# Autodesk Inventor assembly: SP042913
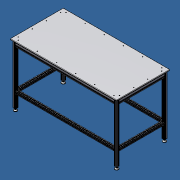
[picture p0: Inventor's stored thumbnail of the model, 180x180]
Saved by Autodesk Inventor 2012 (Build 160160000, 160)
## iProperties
Created: 2013-04
Part Number: SP042913
Document SubType Name: Assembly
Designer: Admin
Author: Admin
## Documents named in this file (8)
- C:\Andys Backup Data\ANDY'S INVENTOR\INVENTOR LIBRARIES\ASSEMBLY LIBRARY\45 SERIES\TABLES_CARTS\SP042913 MEDIUM DUTY TABLE\SP042913 MEDIUM DUTY TABLE.iam
- C:\Andys Backup Data\ANDY'S INVENTOR\INVENTOR LIBRARIES\ASSEMBLY LIBRARY\45 SERIES\TABLES_CARTS\SP042913 MEDIUM DUTY TABLE\SP042913 LEG.ipt
- C:\Andys Backup Data\ANDY'S INVENTOR\INVENTOR LIBRARIES\PARTS LIBRARY\FEET WHEELS FLOOR FASTENING SUPPORTS\21.1881 LEVELING FOOT M8 60mm BASE.iam
- C:\Andys Backup Data\ANDY'S INVENTOR\INVENTOR LIBRARIES\ASSEMBLY LIBRARY\45 SERIES\TABLES_CARTS\SP042913 MEDIUM DUTY TABLE\SP042913 45X90 HORI WIDTH.ipt
- C:\Andys Backup Data\ANDY'S INVENTOR\INVENTOR LIBRARIES\ASSEMBLY LIBRARY\45 SERIES\TABLES_CARTS\SP042913 MEDIUM DUTY TABLE\SP042913 45x90 HORI DEPTH.ipt
- C:\Andys Backup Data\ANDY'S INVENTOR\INVENTOR LIBRARIES\ASSEMBLY LIBRARY\45 SERIES\TABLES_CARTS\SP042913 MEDIUM DUTY TABLE\SP042913 45X45 HORI DEPTH.ipt
- C:\Andys Backup Data\ANDY'S INVENTOR\INVENTOR LIBRARIES\ASSEMBLY LIBRARY\45 SERIES\TABLES_CARTS\SP042913 MEDIUM DUTY TABLE\SP042913 45X45 HORI WIDTH.ipt
- C:\Andys Backup Data\ANDY'S INVENTOR\INVENTOR LIBRARIES\ASSEMBLY LIBRARY\45 SERIES\TABLES_CARTS\SP042913 MEDIUM DUTY TABLE\SP042913 TABLE TOP ASSY.iam
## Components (19 placed, 7 different names)
1. SP042913 LEG:1 — Insert:1, Mate:1, Flush:1, Flush:2, Flush:4, Flush:5, Mate:2, Mate:15, Flush:23
2. 21.1881 LEVELING FOOT M8 60mm BASE:1 [sub-assembly] — Insert:1
3. SP042913 45X90 HORI WIDTH:1 — Mate:1, Flush:1, Flush:2, Mate:9, Flush:17, Mate:17
4. SP042913 45x90 HORI DEPTH:1 — Flush:4, Flush:5, Mate:2, Mate:3, Flush:6, Flush:7, Mate:11
5. SP042913 LEG:2 — Mate:3, Flush:6, Flush:7, Mate:4, Flush:8, Flush:9, Mate:13, Flush:19, Mate:14, Flush:21, Insert:4
6. SP042913 45X90 HORI WIDTH:2 — Mate:4, Flush:8, Flush:9, Mate:5, Flush:10, Flush:11, Mate:8, Flush:16, Mate:16
7. SP042913 LEG:3 — Mate:5, Flush:10, Flush:11, Mate:6, Flush:12, Flush:13, Insert:3
8. SP042913 45x90 HORI DEPTH:2 — Mate:6, Flush:12, Flush:13, Mate:7, Flush:14, Flush:15, Mate:10, Mate:18
9. SP042913 LEG:4 — Mate:7, Flush:14, Flush:15, Mate:12, Flush:18, Insert:2
10. SP042913 45X45 HORI DEPTH:1 — Mate:8, Flush:16, Mate:11
11. SP042913 45X45 HORI DEPTH:2 — Mate:9, Flush:17, Mate:10
12. SP042913 45X45 HORI DEPTH:3 — Mate:12, Flush:18, Flush:20
13. SP042913 45X45 HORI DEPTH:4 — Mate:13, Flush:19, Flush:20, Flush:22, Flush:24
14. SP042913 45X45 HORI WIDTH:1 — Mate:14, Flush:21, Flush:22
15. SP042913 45X45 HORI WIDTH:2 — Mate:15, Flush:23, Flush:24
16. 21.1881 LEVELING FOOT M8 60mm BASE:2 [sub-assembly] — Insert:2
17. 21.1881 LEVELING FOOT M8 60mm BASE:3 [sub-assembly] — Insert:3
18. 21.1881 LEVELING FOOT M8 60mm BASE:4 [sub-assembly] — Insert:4
19. SP042913 TABLE TOP ASSY:1 [sub-assembly] — Mate:16, Mate:17, Mate:18
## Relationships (45: Flush 23, Mate 18, Insert 4)
- Insert:1: SP042913 LEG:1 ↔ 21.1881 LEVELING FOOT M8 60mm BASE:1
- Mate:1: SP042913 LEG:1 ↔ SP042913 45X90 HORI WIDTH:1
- Flush:1: SP042913 LEG:1 ↔ SP042913 45X90 HORI WIDTH:1
- Flush:2: SP042913 LEG:1 ↔ SP042913 45X90 HORI WIDTH:1
- Flush:4: SP042913 LEG:1 ↔ SP042913 45x90 HORI DEPTH:1
- Flush:5: SP042913 LEG:1 ↔ SP042913 45x90 HORI DEPTH:1
- Mate:2: SP042913 LEG:1 ↔ SP042913 45x90 HORI DEPTH:1
- Mate:3: SP042913 45x90 HORI DEPTH:1 ↔ SP042913 LEG:2
- Flush:6: SP042913 45x90 HORI DEPTH:1 ↔ SP042913 LEG:2
- Flush:7: SP042913 45x90 HORI DEPTH:1 ↔ SP042913 LEG:2
- Mate:4: SP042913 LEG:2 ↔ SP042913 45X90 HORI WIDTH:2
- Flush:8: SP042913 LEG:2 ↔ SP042913 45X90 HORI WIDTH:2
- Flush:9: SP042913 LEG:2 ↔ SP042913 45X90 HORI WIDTH:2
- Mate:5: SP042913 45X90 HORI WIDTH:2 ↔ SP042913 LEG:3
- Flush:10: SP042913 45X90 HORI WIDTH:2 ↔ SP042913 LEG:3
- Flush:11: SP042913 45X90 HORI WIDTH:2 ↔ SP042913 LEG:3
- Mate:6: SP042913 LEG:3 ↔ SP042913 45x90 HORI DEPTH:2
- Flush:12: SP042913 LEG:3 ↔ SP042913 45x90 HORI DEPTH:2
- Flush:13: SP042913 LEG:3 ↔ SP042913 45x90 HORI DEPTH:2
- Mate:7: SP042913 45x90 HORI DEPTH:2 ↔ SP042913 LEG:4
- Flush:14: SP042913 45x90 HORI DEPTH:2 ↔ SP042913 LEG:4
- Flush:15: SP042913 45x90 HORI DEPTH:2 ↔ SP042913 LEG:4
- Mate:8: SP042913 45X90 HORI WIDTH:2 ↔ SP042913 45X45 HORI DEPTH:1
- Flush:16: SP042913 45X90 HORI WIDTH:2 ↔ SP042913 45X45 HORI DEPTH:1
- Mate:9: SP042913 45X90 HORI WIDTH:1 ↔ SP042913 45X45 HORI DEPTH:2
- Flush:17: SP042913 45X90 HORI WIDTH:1 ↔ SP042913 45X45 HORI DEPTH:2
- Mate:10: SP042913 45x90 HORI DEPTH:2 ↔ SP042913 45X45 HORI DEPTH:2
- Mate:11: SP042913 45x90 HORI DEPTH:1 ↔ SP042913 45X45 HORI DEPTH:1
- Mate:12: SP042913 LEG:4 ↔ SP042913 45X45 HORI DEPTH:3
- Flush:18: SP042913 LEG:4 ↔ SP042913 45X45 HORI DEPTH:3
- Mate:13: SP042913 LEG:2 ↔ SP042913 45X45 HORI DEPTH:4
- Flush:19: SP042913 LEG:2 ↔ SP042913 45X45 HORI DEPTH:4
- Flush:20: SP042913 45X45 HORI DEPTH:3 ↔ SP042913 45X45 HORI DEPTH:4
- Mate:14: SP042913 LEG:2 ↔ SP042913 45X45 HORI WIDTH:1
- Flush:21: SP042913 LEG:2 ↔ SP042913 45X45 HORI WIDTH:1
- Flush:22: SP042913 45X45 HORI DEPTH:4 ↔ SP042913 45X45 HORI WIDTH:1
- Mate:15: SP042913 LEG:1 ↔ SP042913 45X45 HORI WIDTH:2
- Flush:23: SP042913 LEG:1 ↔ SP042913 45X45 HORI WIDTH:2
- Flush:24: SP042913 45X45 HORI DEPTH:4 ↔ SP042913 45X45 HORI WIDTH:2
- Insert:2: SP042913 LEG:4 ↔ 21.1881 LEVELING FOOT M8 60mm BASE:2
- Insert:3: SP042913 LEG:3 ↔ 21.1881 LEVELING FOOT M8 60mm BASE:3
- Insert:4: SP042913 LEG:2 ↔ 21.1881 LEVELING FOOT M8 60mm BASE:4
- Mate:16: SP042913 45X90 HORI WIDTH:2 ↔ SP042913 TABLE TOP ASSY:1
- Mate:17: SP042913 45X90 HORI WIDTH:1 ↔ SP042913 TABLE TOP ASSY:1
- Mate:18: SP042913 45x90 HORI DEPTH:2 ↔ SP042913 TABLE TOP ASSY:1
## Named parameters: Height = 1066.8 mm, Width = 1828.8 mm, DEPTH = 914.4 mm, LOWER_INSET = 203.2 mm, TABLE_TOP_THICKNESS = 12.7 mm, LEVELER_HEIGHT = 44.45 mm, TOP_OVERHANG = 25.4 mm
